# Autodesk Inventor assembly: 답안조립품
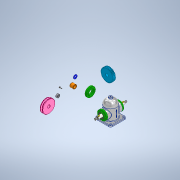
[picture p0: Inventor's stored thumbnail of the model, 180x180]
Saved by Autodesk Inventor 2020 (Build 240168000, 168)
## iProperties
Created: 2021-07
Part Number: 답안조립품
Document SubType Name: Assembly
Designer: Owner
Author: Owner
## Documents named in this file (15)
- C:\Users\Owner\Desktop\710716V1006\답안조립품.iam
- C:\Users\Owner\Desktop\710716V1006\본체.ipt
- C:\Users\Owner\Desktop\710716V1006\V-벨트풀리.ipt
- V-벨트풀리.ipt
- C:\Users\Owner\Desktop\710716V1006\너트 M12x1.25.ipt
- C:\Users\Owner\Desktop\710716V1006\베어링 6203.ipt
- C:\Users\Owner\Desktop\710716V1006\볼트 M4.ipt
- C:\Users\Owner\Desktop\710716V1006\부시.ipt
- C:\Users\Owner\Desktop\710716V1006\스퍼기어.ipt
- C:\Users\Owner\Desktop\710716V1006\오일 실 26 38 8.ipt
- C:\Users\Owner\Desktop\710716V1006\와셔 12x24.ipt
- C:\Users\Owner\Desktop\710716V1006\축.ipt
- C:\Users\Owner\Desktop\710716V1006\커버.ipt
- C:\Users\Owner\Desktop\710716V1006\키 5x5x12.ipt
- C:\Users\Owner\Desktop\710716V1006\커버_MIR.ipt
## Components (1 placed, 1 different names)
1. V-벨트풀리:1
